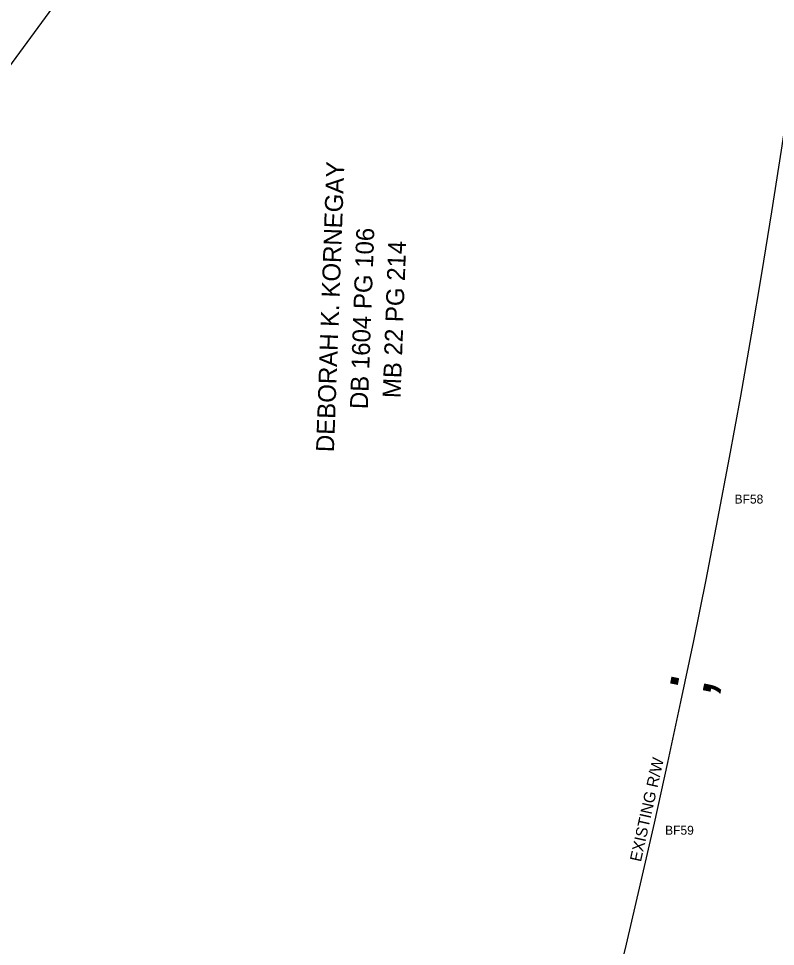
# Model space of a CAD drawing. Extents: x 2262665 to 2270527, y 505476 to 514960.
# Drawn here: x 2265946.4 to 2266157.3, y 509720 to 509978.6 of the extents above; entities that cross this region are included whole.
import ezdxf

# ---------------------------------------------------------------- set-up
doc = ezdxf.new("R2010")
doc.units = 0
for name, color, linetype in [('Exist Horizontal Alignment', 7, 'Continuous'), ('Exist Property Corner Cogo Number', 7, 'Continuous'), ('Exist Property Owner Text', 7, 'Continuous'), ('Exist Right of Way Control of Access CA Symbol CELL', 7, 'Continuous'), ('Exist Right of Way Control of Access Line', 7, 'Continuous'), ('Exist Right of Way Line', 7, 'Continuous'), ('Exist Right of Way Line Text', 7, 'Continuous')]:
    doc.layers.add(name, color=color, linetype=linetype)

msp = doc.modelspace()

# ---------------------------------------------------------------- linework, layer by layer
at = {"layer": 'Exist Horizontal Alignment'}
msp.add_arc((2263436.25, 510359.19), 2882, 309.60499, 355.6461, dxfattribs=at)
at = {"layer": 'Exist Right of Way Control of Access CA Symbol CELL'}
msp.add_line((2266133.03, 509798), (2266133.03, 509798), dxfattribs=at)
at = {"layer": 'Exist Right of Way Control of Access Line'}
msp.add_arc((2263436.25, 510359.19), 2754.56, 309.60499, 355.6461, dxfattribs=at)
at = {"layer": 'Exist Right of Way Line'}
msp.add_line((2266927.92, 511303.77), (2265541.79, 509418.49), dxfattribs=at)

# ---------------------------------------------------------------- texts
at = {"layer": 'Exist Property Corner Cogo Number'}
for s, p in [('BF58', (2266145.93, 509843.41)), ('BF59', (2266126.57, 509751.1))]:
    msp.add_text(s, height=2.5, dxfattribs=at).set_placement(p)
at = {"layer": 'Exist Property Owner Text'}
for s, p in [('DEBORAH K. KORNEGAY', (2266034.3, 509857.68)), ('DB 1604 PG 106', (2266043.74, 509869.67)), ('MB 22 PG 214', (2266052.86, 509872.73))]:
    msp.add_text(s, height=5, rotation=87.9223, dxfattribs=at).set_placement(p)
at = {"layer": 'Exist Right of Way Control of Access CA Symbol CELL'}
msp.add_text(';', height=15, rotation=78.2752, dxfattribs=at).set_placement((2266138.85, 509789.13))
at = {"layer": 'Exist Right of Way Line Text'}
msp.add_text('EXISTING R/W', height=3.2, rotation=77.4224, dxfattribs=at).set_placement((2266119.82, 509743.38))

doc.saveas('drawing.dxf')
